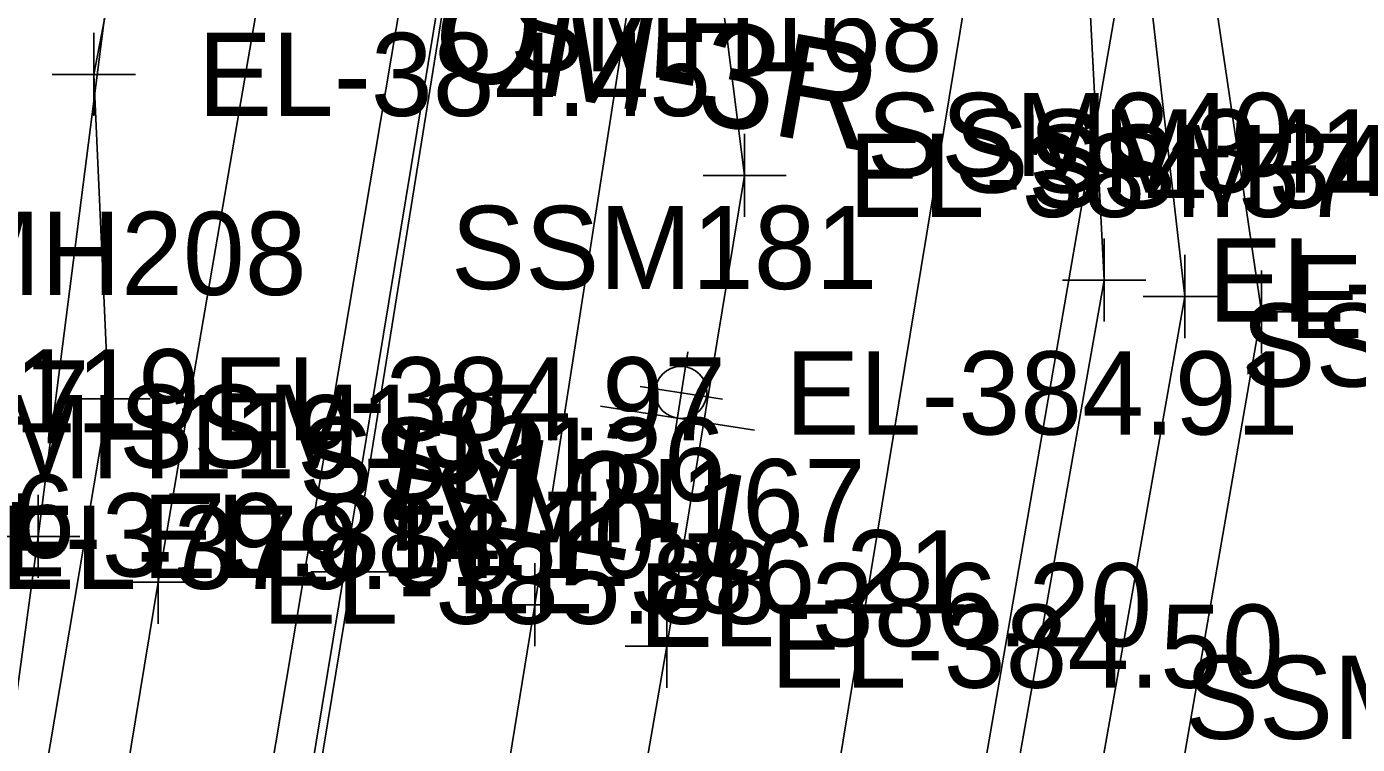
# Model space of a CAD drawing. Extents: x 1189978 to 1314812, y 571533 to 629339.
# Drawn here: x 1217556.1 to 1217620.1, y 621634.2 to 621668.7 of the extents above; entities that cross this region are included whole.
import ezdxf

# ---------------------------------------------------------------- set-up
doc = ezdxf.new("R2010")
doc.units = 0
for name, color, linetype in [('SURVEY - CENTERLINE - Preliminary', 7, 'Continuous'), ('SURVEY - DRAINAGE - Area Shapes', 7, 'Continuous'), ('SURVEY - DRAINAGE - Bridge Hydraulic Data with Text', 7, 'Continuous'), ('SURVEY - DTM - Breaklines', 7, 'Continuous'), ('SURVEY - DTM - Breaklines - Points - Elevations', 7, 'Continuous'), ('SURVEY - DTM - Breaklines - Points - Locators', 7, 'Continuous'), ('SURVEY - DTM - Breaklines - Points - Numbers', 7, 'Continuous'), ('SURVEY - PROPERTY - ROW Lines', 7, 'Continuous'), ('SURVEY - TRAFFIC CONTROL - Signs - Points - Elevations', 7, 'Continuous'), ('SURVEY - TRAFFIC CONTROL - Signs - Points - Locators', 7, 'Continuous'), ('SURVEY - TRAFFIC CONTROL - Signs - Points - Numbers', 7, 'Continuous'), ('SURVEY - TRAFFIC CONTROL - Signs and Devices with Text', 7, 'Continuous'), ('SURVEY - TRANSPORTATION - Roads', 7, 'Continuous'), ('SURVEY - TRANSPORTATION - Roads - Points - Elevations', 7, 'Continuous'), ('SURVEY - TRANSPORTATION - Roads - Points - Locators', 7, 'Continuous'), ('SURVEY - TRANSPORTATION - Roads - Points - Numbers', 7, 'Continuous'), ('SURVEY - UTILITIES - Electric (Overhead) with Text', 7, 'Continuous'), ('SURVEY - VEGETATION - Features - Points - Elevations', 7, 'Continuous'), ('SURVEY - VEGETATION - Features - Points - Locators', 7, 'Continuous'), ('SURVEY - VEGETATION - Features - Points - Numbers', 7, 'Continuous'), ('SURVEY - VEGETATION - Features with Text', 7, 'Continuous')]:
    doc.layers.add(name, color=color, linetype=linetype)

msp = doc.modelspace()

# ---------------------------------------------------------------- linework, layer by layer
at = {"layer": 'SURVEY - CENTERLINE - Preliminary'}
msp.add_line((1217525.369, 621363.652), (1217649.691, 622116.549), dxfattribs=at)
msp.add_line((1217525.369, 621363.652), (1217649.691, 622116.549), dxfattribs=at)
at = {"layer": 'SURVEY - DRAINAGE - Area Shapes'}
msp.add_line((1217415.87, 620731.677), (1218149.356, 625079.901), dxfattribs=at)
at = {"layer": 'SURVEY - DRAINAGE - Bridge Hydraulic Data with Text'}
for p, q in [((1217590.674, 621663.547), (1217590.674, 621659.547)), ((1217592.674, 621661.547), (1217588.674, 621661.547)), ((1217586.923, 621640.897), (1217586.923, 621636.897)), ((1217588.923, 621638.897), (1217584.923, 621638.897))]:
    msp.add_line(p, q, dxfattribs=at)
msp.add_lwpolyline([(1217505.541, 621026.787), (1217497.333, 621030.975), (1217494.441, 621038.225), (1217497.197, 621080.447), (1217509.012, 621144.375), (1217516.683, 621191.707), (1217524.088, 621241.487), (1217533.148, 621294.149), (1217540.613, 621345.967), (1217548.019, 621393.692), (1217553.923, 621442.077), (1217565.443, 621490.609), (1217569.703, 621540.294), (1217578.32, 621589.372), (1217586.923, 621638.897), (1217590.674, 621661.547), (1217589.093, 621673.953), (1217587.376, 621675.539)], dxfattribs=at)
at = {"layer": 'SURVEY - DTM - Breaklines'}
for points in [[(1217510.22, 621032.466), (1217510.666, 621035.51), (1217516.561, 621076.889), (1217522.631, 621118.367), (1217524.367, 621130.68), (1217531.058, 621153.323), (1217534.842, 621195.274), (1217541.126, 621235.576), (1217547.862, 621274.248), (1217552.158, 621315.032), (1217559.393, 621352.713), (1217565.052, 621392.347), (1217570.591, 621431.174), (1217579.736, 621465.575), (1217585.386, 621503.247), (1217588.033, 621516.541), (1217587.874, 621544.34), (1217597.398, 621586.777), (1217605.23, 621618.412), (1217611.845, 621655.717), (1217609.15, 621679.367), (1217607.176, 621692.622), (1217600.47, 621698.352)], [(1217510.22, 621032.466), (1217512.118, 621031.066), (1217514.392, 621035.673), (1217519.346, 621076.453), (1217525.784, 621118.115), (1217527.237, 621129.566), (1217533.801, 621152.906), (1217537.057, 621194.249), (1217544.11, 621234.911), (1217551.917, 621273.847), (1217555.69, 621314.912), (1217562.5, 621351.442), (1217567.375, 621391.584), (1217573.292, 621430.4), (1217583.026, 621465.145), (1217587.758, 621502.698), (1217590.388, 621516.14), (1217590.712, 621543.439), (1217600.324, 621586.265), (1217609.153, 621618.283), (1217615.532, 621654.978), (1217611.843, 621679.951), (1217608.976, 621694.451), (1217608.754, 621696.579)], [(1217510.581, 621028.062), (1217508.117, 621030.69), (1217507.014, 621036.891), (1217513.628, 621077.21), (1217519.368, 621118.671), (1217522.532, 621131.005), (1217528.606, 621154.695), (1217531.085, 621195.411), (1217537.781, 621236.297), (1217543.579, 621274.681), (1217548.508, 621316.14), (1217556.966, 621353.312), (1217561.878, 621392.988), (1217568.359, 621432.007), (1217577.69, 621466.223), (1217582.727, 621504.231), (1217584.246, 621517.153), (1217585.602, 621545.348), (1217593.929, 621587.236), (1217602.313, 621624.581), (1217607.967, 621656.511), (1217606.788, 621679.184), (1217604.88, 621690.789), (1217551.165, 621685.802)], [(1217567.585, 621678.778), (1217566.649, 621676.805), (1217561.057, 621675.087), (1217559.372, 621666.405), (1217560.082, 621650.794), (1217551.976, 621602.783), (1217540.514, 621551.928), (1217533.572, 621500.328), (1217524.406, 621453.509), (1217516.182, 621399.789), (1217505.655, 621346.606), (1217497.912, 621291.916), (1217486.508, 621241.583), (1217479.657, 621189.93), (1217471.353, 621146.025), (1217465.62, 621095.905), (1217456.922, 621043.819), (1217448.307, 620989.836), (1217436.809, 620938.632)], [(1217418.055, 620739.441), (1217427.36, 620792.564), (1217436.718, 620845.046), (1217446.216, 620900.311), (1217455.61, 620954.21), (1217464.256, 621004.542), (1217473.295, 621056.894), (1217481.829, 621108.046), (1217491.344, 621163.825), (1217500.426, 621216.55), (1217508.984, 621267.021), (1217518.361, 621323.371), (1217527.289, 621375.807), (1217536.188, 621428.966), (1217544.911, 621481.658), (1217554.382, 621538.383), (1217563.543, 621592.413), (1217571.82, 621642.476), (1217577.37, 621677.13)]]:
    msp.add_lwpolyline(points, dxfattribs=at)
at = {"layer": 'SURVEY - DTM - Breaklines - Points - Locators'}
for p, q in [((1217559.372, 621668.405), (1217559.372, 621664.405)), ((1217561.372, 621666.405), (1217557.372, 621666.405)), ((1217607.967, 621658.511), (1217607.967, 621654.511)), ((1217611.845, 621657.717), (1217611.845, 621653.717)), ((1217615.532, 621656.978), (1217615.532, 621652.978)), ((1217609.967, 621656.511), (1217605.967, 621656.511)), ((1217613.845, 621655.717), (1217609.845, 621655.717)), ((1217617.532, 621654.978), (1217613.532, 621654.978)), ((1217560.082, 621652.794), (1217560.082, 621648.794)), ((1217562.082, 621650.794), (1217558.082, 621650.794)), ((1217571.82, 621644.476), (1217571.82, 621640.476)), ((1217573.82, 621642.476), (1217569.82, 621642.476))]:
    msp.add_line(p, q, dxfattribs=at)
at = {"layer": 'SURVEY - PROPERTY - ROW Lines'}
msp.add_line((1217606.404, 621700.951), (1217550.035, 621359.579), dxfattribs=at)
at = {"layer": 'SURVEY - TRAFFIC CONTROL - Signs - Points - Locators'}
for p, q in [((1217587.935, 621653.056), (1217587.323, 621649.102)), ((1217585.652, 621651.385), (1217589.606, 621650.773))]:
    msp.add_line(p, q, dxfattribs=at)
at = {"layer": 'SURVEY - TRAFFIC CONTROL - Signs and Devices with Text'}
msp.add_line((1217591.148, 621649.296), (1217583.736, 621650.442), dxfattribs=at)
msp.add_circle((1217587.612, 621651.107), 1.25, dxfattribs=at)
at = {"layer": 'SURVEY - TRANSPORTATION - Roads'}
for points in [[(1217409.505, 620742.513), (1217418.873, 620794.586), (1217428.101, 620847.792), (1217437.405, 620901.382), (1217446.452, 620953.249), (1217455.441, 621005.601), (1217463.888, 621055.837), (1217472.904, 621108.559), (1217482.309, 621162.334), (1217491.187, 621215.01), (1217500.52, 621270.573), (1217509.548, 621324.4), (1217518.06, 621374.089), (1217518.815, 621378.636), (1217527.27, 621430.435), (1217535.853, 621480.993), (1217545.481, 621538.854), (1217553.738, 621589.36), (1217562.469, 621641.973), (1217568.753, 621678.537), (1217567.585, 621678.778)], [(1217427.253, 620738.215), (1217436.587, 620791.336), (1217445.336, 620842.588), (1217455.149, 620898.884), (1217464.251, 620950.623), (1217473.386, 621002.581), (1217480.67, 621046.801), (1217490.831, 621106.731), (1217500.223, 621160.546), (1217509.525, 621215.717), (1217518.405, 621266.503), (1217527.502, 621321.852), (1217536.343, 621374.244), (1217563.482, 621537.918), (1217572.048, 621588.602), (1217580.584, 621640.89), (1217586, 621675.746), (1217587.376, 621675.539)]]:
    msp.add_lwpolyline(points, dxfattribs=at)
at = {"layer": 'SURVEY - TRANSPORTATION - Roads - Points - Locators'}
for p, q in [((1217562.469, 621643.973), (1217562.469, 621639.973)), ((1217580.584, 621642.89), (1217580.584, 621638.89)), ((1217564.469, 621641.973), (1217560.469, 621641.973)), ((1217582.584, 621640.89), (1217578.584, 621640.89))]:
    msp.add_line(p, q, dxfattribs=at)
at = {"layer": 'SURVEY - UTILITIES - Electric (Overhead) with Text'}
msp.add_lwpolyline([(1217806.135, 622776.996), (1217743.095, 622422.637), (1217688.195, 622113.294), (1217626.828, 621775.192), (1217569.139, 621442.226), (1217508.827, 621100.018), (1217448.236, 620751.9)], dxfattribs=at)
at = {"layer": 'SURVEY - VEGETATION - Features - Points - Locators'}
for p, q in [((1217556.696, 621646.18), (1217556.696, 621642.18)), ((1217558.696, 621644.18), (1217554.696, 621644.18))]:
    msp.add_line(p, q, dxfattribs=at)
at = {"layer": 'SURVEY - VEGETATION - Features with Text'}
msp.add_lwpolyline([(1217560.76, 621675.932), (1217556.696, 621644.18), (1217551.372, 621604.871), (1217540.799, 621553.119), (1217537.154, 621511.965), (1217530.134, 621471.539), (1217522.438, 621431.382), (1217515.901, 621389.365), (1217510.937, 621348.813), (1217502.944, 621307.056), (1217494.555, 621266.124), (1217486.373, 621220.88), (1217482.404, 621178.781), (1217475.754, 621141.847), (1217465.346, 621099.732), (1217457.546, 621059.446), (1217452.151, 621021.565), (1217443.784, 620977.068), (1217434.585, 620932.466)], dxfattribs=at)

# ---------------------------------------------------------------- texts
at = {"layer": 'SURVEY - DTM - Breaklines - Points - Elevations'}
for s, p in [('EL-384.45', (1217564.372, 621664.405)), ('EL-384.57', (1217595.674, 621659.547)), ('EL-374.97', (1217612.967, 621654.511)), ('EL-374.37', (1217616.845, 621653.717)), ('EL-384.97', (1217565.082, 621648.794)), ('EL-387.76', (1217533.78, 621643.146)), ('EL-379.81', (1217551.429, 621642.249)), ('EL-379.56', (1217554.89, 621641.65)), ('EL-386.21', (1217576.82, 621640.476)), ('EL-384.50', (1217591.923, 621636.897))]:
    msp.add_text(s, height=4, dxfattribs=at).set_placement(p)
at = {"layer": 'SURVEY - DTM - Breaklines - Points - Numbers'}
for s, p in [('SMH168', (1217579.387, 621666.547)), ('SSM340', (1217596.554, 621661.511)), ('SSM341', (1217600.763, 621660.717)), ('SSM342', (1217604.292, 621659.978)), ('SMH208', (1217548.795, 621655.794)), ('SSM223', (1217614.56, 621651.385)), ('SMA147', (1217538.65, 621648.65)), ('SSM135', (1217560.581, 621647.476)), ('SMH167', (1217575.683, 621643.897)), ('SSM222', (1217611.843, 621634.437))]:
    msp.add_text(s, height=4, dxfattribs=at).set_placement(p)
at = {"layer": 'SURVEY - TRAFFIC CONTROL - Signs - Points - Elevations'}
msp.add_text('EL-384.91', height=4, dxfattribs=at).set_placement((1217592.629, 621649.079))
at = {"layer": 'SURVEY - TRAFFIC CONTROL - Signs - Points - Numbers'}
msp.add_text('SSM181', height=4, dxfattribs=at).set_placement((1217576.547, 621656.079))
at = {"layer": 'SURVEY - TRAFFIC CONTROL - Signs and Devices with Text'}
for s, p in [('OM-3R', (1217575.381, 621666.459)), ('R12-1', (1217573.132, 621645.122))]:
    msp.add_text(s, height=5, rotation=349.88791, dxfattribs=at).set_placement(p)
at = {"layer": 'SURVEY - TRANSPORTATION - Roads - Points - Elevations'}
for s, p in [('EL-385.88', (1217567.469, 621639.973)), ('EL-386.20', (1217585.584, 621638.89))]:
    msp.add_text(s, height=4, dxfattribs=at).set_placement(p)
at = {"layer": 'SURVEY - TRANSPORTATION - Roads - Points - Numbers'}
for s, p in [('SMH119', (1217551.214, 621646.973)), ('SSM136', (1217569.234, 621645.89))]:
    msp.add_text(s, height=4, dxfattribs=at).set_placement(p)
at = {"layer": 'SURVEY - VEGETATION - Features - Points - Elevations'}
msp.add_text('EL-384.10', height=4, dxfattribs=at).set_placement((1217561.696, 621642.18))
at = {"layer": 'SURVEY - VEGETATION - Features - Points - Numbers'}
msp.add_text('SJR119', height=4, dxfattribs=at).set_placement((1217545.441, 621649.18))

doc.saveas('drawing.dxf')
